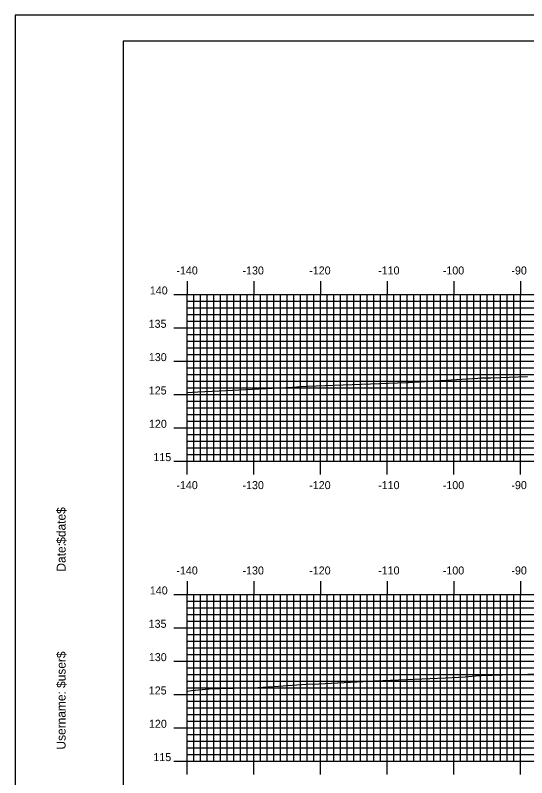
# Model space of a CAD drawing. Extents: x 841782 to 842125, y 363538 to 363758.
# Drawn here: x 841781.6 to 841858.3, y 363643.2 to 363757.6 of the extents above; entities that cross this region are included whole.
import ezdxf

# ---------------------------------------------------------------- set-up
doc = ezdxf.new("R2010")
doc.units = 0
for name, color, linetype in [('BORDER', 7, 'Continuous'), ('H_V ANNOTATION', 7, 'Continuous'), ('M_Roadway_Centerline', 7, 'Continuous'), ('MAJOR', 7, 'Continuous'), ('MINOR', 7, 'Continuous'), ('PLOT BOUNDARY', 7, 'Continuous'), ('S_Roadway_Centerline', 7, 'Continuous')]:
    doc.layers.add(name, color=color, linetype=linetype)

msp = doc.modelspace()

# ---------------------------------------------------------------- linework, layer by layer
at = {"layer": 'BORDER'}
msp.add_lwpolyline([(841797.77, 363543.72), (842117.77, 363543.72), (842117.77, 363753.72), (841797.77, 363753.72)], close=True, dxfattribs=at)
at = {"layer": 'MAJOR'}
for p, q in [((841807.37, 363717.73), (841807.37, 363715.72)), ((841817.37, 363717.73), (841817.37, 363715.72)), ((841827.37, 363717.73), (841827.37, 363715.72)), ((841837.37, 363717.73), (841837.37, 363715.72)), ((841847.37, 363717.73), (841847.37, 363715.72)), ((841857.37, 363717.73), (841857.37, 363715.72)), ((841805.37, 363715.72), (841807.37, 363715.72)), ((841807.37, 363715.72), (842087.37, 363715.72)), ((841807.37, 363690.72), (841807.37, 363715.72)), ((841807.37, 363690.72), (841807.37, 363715.72)), ((841807.37, 363715.72), (842087.37, 363715.72)), ((841817.37, 363690.72), (841817.37, 363715.72)), ((841827.37, 363690.72), (841827.37, 363715.72)), ((841837.37, 363690.72), (841837.37, 363715.72)), ((841847.37, 363690.72), (841847.37, 363715.72)), ((841857.37, 363690.72), (841857.37, 363715.72)), ((841805.37, 363710.72), (841807.37, 363710.72)), ((841807.37, 363710.72), (842087.37, 363710.72)), ((841805.37, 363705.72), (841807.37, 363705.72)), ((841807.37, 363705.72), (842087.37, 363705.72)), ((841805.37, 363700.72), (841807.37, 363700.72)), ((841807.37, 363700.72), (842087.37, 363700.72)), ((841805.37, 363695.72), (841807.37, 363695.72)), ((841807.37, 363695.72), (842087.37, 363695.72)), ((841805.37, 363690.72), (841807.37, 363690.72)), ((841807.37, 363690.72), (842087.37, 363690.72)), ((841807.37, 363690.72), (842087.37, 363690.72)), ((841807.37, 363688.72), (841807.37, 363690.72)), ((841817.37, 363688.72), (841817.37, 363690.72)), ((841827.37, 363688.72), (841827.37, 363690.72)), ((841837.37, 363688.72), (841837.37, 363690.72)), ((841847.37, 363688.72), (841847.37, 363690.72)), ((841857.37, 363688.72), (841857.37, 363690.72)), ((841807.37, 363672.73), (841807.37, 363670.72)), ((841817.37, 363672.73), (841817.37, 363670.72)), ((841827.37, 363672.73), (841827.37, 363670.72)), ((841837.37, 363672.73), (841837.37, 363670.72)), ((841847.37, 363672.73), (841847.37, 363670.72)), ((841857.37, 363672.73), (841857.37, 363670.72)), ((841805.37, 363670.72), (841807.37, 363670.72)), ((841807.37, 363670.72), (842087.37, 363670.72)), ((841807.37, 363645.72), (841807.37, 363670.72)), ((841807.37, 363645.72), (841807.37, 363670.72)), ((841807.37, 363670.72), (842087.37, 363670.72)), ((841817.37, 363645.72), (841817.37, 363670.72)), ((841827.37, 363645.72), (841827.37, 363670.72)), ((841837.37, 363645.72), (841837.37, 363670.72)), ((841847.37, 363645.72), (841847.37, 363670.72)), ((841857.37, 363645.72), (841857.37, 363670.72)), ((841805.37, 363665.72), (841807.37, 363665.72)), ((841807.37, 363665.72), (842087.37, 363665.72)), ((841805.37, 363660.72), (841807.37, 363660.72)), ((841807.37, 363660.72), (842087.37, 363660.72)), ((841805.37, 363655.72), (841807.37, 363655.72)), ((841807.37, 363655.72), (842087.37, 363655.72)), ((841805.37, 363650.72), (841807.37, 363650.72)), ((841807.37, 363650.72), (842087.37, 363650.72)), ((841805.37, 363645.72), (841807.37, 363645.72)), ((841807.37, 363645.72), (842087.37, 363645.72)), ((841807.37, 363645.72), (842087.37, 363645.72)), ((841807.37, 363643.72), (841807.37, 363645.72)), ((841817.37, 363643.72), (841817.37, 363645.72)), ((841827.37, 363643.72), (841827.37, 363645.72)), ((841837.37, 363643.72), (841837.37, 363645.72)), ((841847.37, 363643.72), (841847.37, 363645.72)), ((841857.37, 363643.72), (841857.37, 363645.72))]:
    msp.add_line(p, q, dxfattribs=at)
at = {"layer": 'MINOR'}
for p, q in [((841808.37, 363690.72), (841808.37, 363715.72)), ((841809.37, 363690.72), (841809.37, 363715.72)), ((841810.37, 363690.72), (841810.37, 363715.72)), ((841811.37, 363690.72), (841811.37, 363715.72)), ((841812.37, 363690.72), (841812.37, 363715.72)), ((841813.37, 363690.72), (841813.37, 363715.72)), ((841814.37, 363690.72), (841814.37, 363715.72)), ((841815.37, 363690.72), (841815.37, 363715.72)), ((841816.37, 363690.72), (841816.37, 363715.72)), ((841818.37, 363690.72), (841818.37, 363715.72)), ((841819.37, 363690.72), (841819.37, 363715.72)), ((841820.37, 363690.72), (841820.37, 363715.72)), ((841821.37, 363690.72), (841821.37, 363715.72)), ((841822.37, 363690.72), (841822.37, 363715.72)), ((841823.37, 363690.72), (841823.37, 363715.72)), ((841824.37, 363690.72), (841824.37, 363715.72)), ((841825.37, 363690.72), (841825.37, 363715.72)), ((841826.37, 363690.72), (841826.37, 363715.72)), ((841828.37, 363690.72), (841828.37, 363715.72)), ((841829.37, 363690.72), (841829.37, 363715.72)), ((841830.37, 363690.72), (841830.37, 363715.72)), ((841831.37, 363690.72), (841831.37, 363715.72)), ((841832.37, 363690.72), (841832.37, 363715.72)), ((841833.37, 363690.72), (841833.37, 363715.72)), ((841834.37, 363690.72), (841834.37, 363715.72)), ((841835.37, 363690.72), (841835.37, 363715.72)), ((841836.37, 363690.72), (841836.37, 363715.72)), ((841838.37, 363690.72), (841838.37, 363715.72)), ((841839.37, 363690.72), (841839.37, 363715.72)), ((841840.37, 363690.72), (841840.37, 363715.72)), ((841841.37, 363690.72), (841841.37, 363715.72)), ((841842.37, 363690.72), (841842.37, 363715.72)), ((841843.37, 363690.72), (841843.37, 363715.72)), ((841844.37, 363690.72), (841844.37, 363715.72)), ((841845.37, 363690.72), (841845.37, 363715.72)), ((841846.37, 363690.72), (841846.37, 363715.72)), ((841848.37, 363690.72), (841848.37, 363715.72)), ((841849.37, 363690.72), (841849.37, 363715.72)), ((841850.37, 363690.72), (841850.37, 363715.72)), ((841851.37, 363690.72), (841851.37, 363715.72)), ((841852.37, 363690.72), (841852.37, 363715.72)), ((841853.37, 363690.72), (841853.37, 363715.72)), ((841854.37, 363690.72), (841854.37, 363715.72)), ((841855.37, 363690.72), (841855.37, 363715.72)), ((841856.37, 363690.72), (841856.37, 363715.72)), ((841807.37, 363714.72), (842087.37, 363714.72)), ((841807.37, 363714.72), (841809.38, 363714.72)), ((841807.37, 363713.72), (842087.37, 363713.72)), ((841807.37, 363713.72), (841809.38, 363713.72)), ((841807.37, 363712.72), (842087.37, 363712.72)), ((841807.37, 363712.72), (841809.38, 363712.72)), ((841807.37, 363711.72), (842087.37, 363711.72)), ((841807.37, 363711.72), (841809.38, 363711.72)), ((841807.37, 363709.72), (842087.37, 363709.72)), ((841807.37, 363709.72), (841809.38, 363709.72)), ((841807.37, 363708.72), (842087.37, 363708.72)), ((841807.37, 363708.72), (841809.38, 363708.72)), ((841807.37, 363707.72), (842087.37, 363707.72)), ((841807.37, 363707.72), (841809.38, 363707.72)), ((841807.37, 363706.72), (842087.37, 363706.72)), ((841807.37, 363706.72), (841809.38, 363706.72)), ((841807.37, 363704.72), (842087.37, 363704.72)), ((841807.37, 363704.72), (841809.38, 363704.72)), ((841807.37, 363703.72), (842087.37, 363703.72)), ((841807.37, 363703.72), (841809.38, 363703.72)), ((841807.37, 363702.72), (842087.37, 363702.72)), ((841807.37, 363702.72), (841809.38, 363702.72)), ((841807.37, 363701.72), (842087.37, 363701.72)), ((841807.37, 363701.72), (841809.38, 363701.72)), ((841807.37, 363699.72), (842087.37, 363699.72)), ((841807.37, 363699.72), (841809.38, 363699.72)), ((841807.37, 363698.72), (842087.37, 363698.72)), ((841807.37, 363698.72), (841809.38, 363698.72)), ((841807.37, 363697.72), (842087.37, 363697.72)), ((841807.37, 363697.72), (841809.38, 363697.72)), ((841807.37, 363696.72), (842087.37, 363696.72)), ((841807.37, 363696.72), (841809.38, 363696.72)), ((841807.37, 363694.72), (842087.37, 363694.72)), ((841807.37, 363694.72), (841809.38, 363694.72)), ((841807.37, 363693.72), (842087.37, 363693.72)), ((841807.37, 363693.72), (841809.38, 363693.72)), ((841807.37, 363692.72), (842087.37, 363692.72)), ((841807.37, 363692.72), (841809.38, 363692.72)), ((841807.37, 363691.72), (842087.37, 363691.72)), ((841807.37, 363691.72), (841809.38, 363691.72)), ((841808.37, 363645.72), (841808.37, 363670.72)), ((841809.37, 363645.72), (841809.37, 363670.72)), ((841810.37, 363645.72), (841810.37, 363670.72)), ((841811.37, 363645.72), (841811.37, 363670.72)), ((841812.37, 363645.72), (841812.37, 363670.72)), ((841813.37, 363645.72), (841813.37, 363670.72)), ((841814.37, 363645.72), (841814.37, 363670.72)), ((841815.37, 363645.72), (841815.37, 363670.72)), ((841816.37, 363645.72), (841816.37, 363670.72)), ((841818.37, 363645.72), (841818.37, 363670.72)), ((841819.37, 363645.72), (841819.37, 363670.72)), ((841820.37, 363645.72), (841820.37, 363670.72)), ((841821.37, 363645.72), (841821.37, 363670.72)), ((841822.37, 363645.72), (841822.37, 363670.72)), ((841823.37, 363645.72), (841823.37, 363670.72)), ((841824.37, 363645.72), (841824.37, 363670.72)), ((841825.37, 363645.72), (841825.37, 363670.72)), ((841826.37, 363645.72), (841826.37, 363670.72)), ((841828.37, 363645.72), (841828.37, 363670.72)), ((841829.37, 363645.72), (841829.37, 363670.72)), ((841830.37, 363645.72), (841830.37, 363670.72)), ((841831.37, 363645.72), (841831.37, 363670.72)), ((841832.37, 363645.72), (841832.37, 363670.72)), ((841833.37, 363645.72), (841833.37, 363670.72)), ((841834.37, 363645.72), (841834.37, 363670.72)), ((841835.37, 363645.72), (841835.37, 363670.72)), ((841836.37, 363645.72), (841836.37, 363670.72)), ((841838.37, 363645.72), (841838.37, 363670.72)), ((841839.37, 363645.72), (841839.37, 363670.72)), ((841840.37, 363645.72), (841840.37, 363670.72)), ((841841.37, 363645.72), (841841.37, 363670.72)), ((841842.37, 363645.72), (841842.37, 363670.72)), ((841843.37, 363645.72), (841843.37, 363670.72)), ((841844.37, 363645.72), (841844.37, 363670.72)), ((841845.37, 363645.72), (841845.37, 363670.72)), ((841846.37, 363645.72), (841846.37, 363670.72)), ((841848.37, 363645.72), (841848.37, 363670.72)), ((841849.37, 363645.72), (841849.37, 363670.72)), ((841850.37, 363645.72), (841850.37, 363670.72)), ((841851.37, 363645.72), (841851.37, 363670.72)), ((841852.37, 363645.72), (841852.37, 363670.72)), ((841853.37, 363645.72), (841853.37, 363670.72)), ((841854.37, 363645.72), (841854.37, 363670.72)), ((841855.37, 363645.72), (841855.37, 363670.72)), ((841856.37, 363645.72), (841856.37, 363670.72)), ((841807.37, 363669.72), (842087.37, 363669.72)), ((841807.37, 363669.72), (841809.38, 363669.72)), ((841807.37, 363668.72), (842087.37, 363668.72)), ((841807.37, 363668.72), (841809.38, 363668.72)), ((841807.37, 363667.72), (842087.37, 363667.72)), ((841807.37, 363667.72), (841809.38, 363667.72)), ((841807.37, 363666.72), (842087.37, 363666.72)), ((841807.37, 363666.72), (841809.38, 363666.72)), ((841807.37, 363664.72), (842087.37, 363664.72)), ((841807.37, 363664.72), (841809.38, 363664.72)), ((841807.37, 363663.72), (842087.37, 363663.72)), ((841807.37, 363663.72), (841809.38, 363663.72)), ((841807.37, 363662.72), (842087.37, 363662.72)), ((841807.37, 363662.72), (841809.38, 363662.72)), ((841807.37, 363661.72), (842087.37, 363661.72)), ((841807.37, 363661.72), (841809.38, 363661.72)), ((841807.37, 363659.72), (842087.37, 363659.72)), ((841807.37, 363659.72), (841809.38, 363659.72)), ((841807.37, 363658.72), (842087.37, 363658.72)), ((841807.37, 363658.72), (841809.38, 363658.72)), ((841807.37, 363657.72), (842087.37, 363657.72)), ((841807.37, 363657.72), (841809.38, 363657.72)), ((841807.37, 363656.72), (842087.37, 363656.72)), ((841807.37, 363656.72), (841809.38, 363656.72)), ((841807.37, 363654.72), (842087.37, 363654.72)), ((841807.37, 363654.72), (841809.38, 363654.72)), ((841807.37, 363653.72), (842087.37, 363653.72)), ((841807.37, 363653.72), (841809.38, 363653.72)), ((841807.37, 363652.72), (842087.37, 363652.72)), ((841807.37, 363652.72), (841809.38, 363652.72)), ((841807.37, 363651.72), (842087.37, 363651.72)), ((841807.37, 363651.72), (841809.38, 363651.72)), ((841807.37, 363649.72), (842087.37, 363649.72)), ((841807.37, 363649.72), (841809.38, 363649.72)), ((841807.37, 363648.72), (842087.37, 363648.72)), ((841807.37, 363648.72), (841809.38, 363648.72)), ((841807.37, 363647.72), (842087.37, 363647.72)), ((841807.37, 363647.72), (841809.38, 363647.72)), ((841807.37, 363646.72), (842087.37, 363646.72)), ((841807.37, 363646.72), (841809.38, 363646.72))]:
    msp.add_line(p, q, dxfattribs=at)
at = {"layer": 'PLOT BOUNDARY'}
msp.add_lwpolyline([(841781.59, 363537.6), (842121.59, 363537.6), (842121.59, 363757.6), (841781.59, 363757.6)], close=True, dxfattribs=at)
at = {"layer": 'S_Roadway_Centerline'}
for points in [[(841807.37, 363701.02), (841808.96, 363701.14), (841812.18, 363701.25), (841823.18, 363701.82), (841824.5, 363701.91), (841825.4, 363701.95), (841840.26, 363702.51), (841840.57, 363702.52), (841850.98, 363703.16), (841851.51, 363703.21), (841851.92, 363703.22), (841852.94, 363703.23), (841858.46, 363703.44)], [(841807.37, 363656.2), (841808.05, 363656.32), (841810.67, 363656.57), (841816, 363656.71), (841817.16, 363656.73), (841821.08, 363656.95), (841825.86, 363657.33), (841826.2, 363657.27), (841833.79, 363657.66), (841835.55, 363657.75), (841846.16, 363658.22), (841849.07, 363658.36), (841850.62, 363658.51), (841851.58, 363658.59), (841854.67, 363658.68), (841866.02, 363658.96)]]:
    msp.add_lwpolyline(points, dxfattribs=at)

# ---------------------------------------------------------------- texts
at = {"layer": 'BORDER'}
for s, p in [('$date$', (841789.14, 363678.33)), ('Date:', (841789.14, 363674.15)), ('$user$', (841789.14, 363656.7)), ('Username:', (841789.14, 363647.46))]:
    msp.add_text(s, height=1.339, rotation=90, dxfattribs=at).set_placement(p)
at = {"layer": 'H_V ANNOTATION'}
for s, p in [('-140', (841805.76, 363718.72)), ('-130', (841815.68, 363718.72)), ('-120', (841825.69, 363718.72)), ('-110', (841836.03, 363718.72)), ('-100', (841845.73, 363718.72)), ('-90', (841856.02, 363718.72)), ('140', (841801.78, 363715.72)), ('135', (841801.6, 363710.72)), ('130', (841801.63, 363705.72)), ('125', (841801.62, 363700.72)), ('120', (841801.65, 363695.72)), ('115', (841802.31, 363690.72)), ('-140', (841805.76, 363686.52)), ('-130', (841815.68, 363686.52)), ('-120', (841825.69, 363686.52)), ('-110', (841836.03, 363686.52)), ('-100', (841845.73, 363686.52)), ('-90', (841856.02, 363686.52)), ('-140', (841805.76, 363673.72)), ('-130', (841815.68, 363673.72)), ('-120', (841825.69, 363673.72)), ('-110', (841836.03, 363673.72)), ('-100', (841845.73, 363673.72)), ('-90', (841856.02, 363673.72)), ('140', (841801.78, 363670.72)), ('135', (841801.6, 363665.72)), ('130', (841801.63, 363660.72)), ('125', (841801.62, 363655.72)), ('120', (841801.65, 363650.72)), ('115', (841802.31, 363645.72))]:
    msp.add_text(s, height=1.2, dxfattribs=at).set_placement(p)
at = {"layer": 'M_Roadway_Centerline'}
for s, p in [('C', (841851.5, 363703.21)), ('L', (841851.51, 363703.2)), ('C', (841824.5, 363701.91)), ('L', (841824.5, 363701.91)), ('C', (841851.58, 363658.59)), ('L', (841851.58, 363658.58)), ('C', (841825.85, 363657.33)), ('L', (841825.86, 363657.32))]:
    msp.add_text(s, height=0.0146, dxfattribs=at).set_placement(p)
at = {"layer": 'MAJOR'}
for p in [(841807.36, 363690.72), (841807.36, 363645.72)]:
    msp.add_text('-', height=0.012, dxfattribs=at).set_placement(p)

doc.saveas('drawing.dxf')
